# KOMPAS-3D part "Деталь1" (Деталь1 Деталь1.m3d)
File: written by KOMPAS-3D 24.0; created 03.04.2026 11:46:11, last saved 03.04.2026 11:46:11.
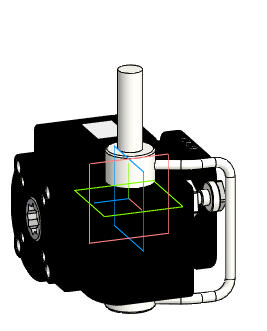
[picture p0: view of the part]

Document properties: Автор: R2D2; Полное имя файла: E:\Работа\Зайцев\Аксессуары для пневмоприводов\Ручной дублер DN.ru\MON1-250-T26-ISO Ручной дублер DN.ru\исходные материалы\Деталь1 Деталь1.m3d

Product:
- Body: Твердое тело1  | qty 1
- Part/product: Деталь1
    additional columns: Типовые

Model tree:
1. Твердое тело1  (labels: Твердое тело1)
